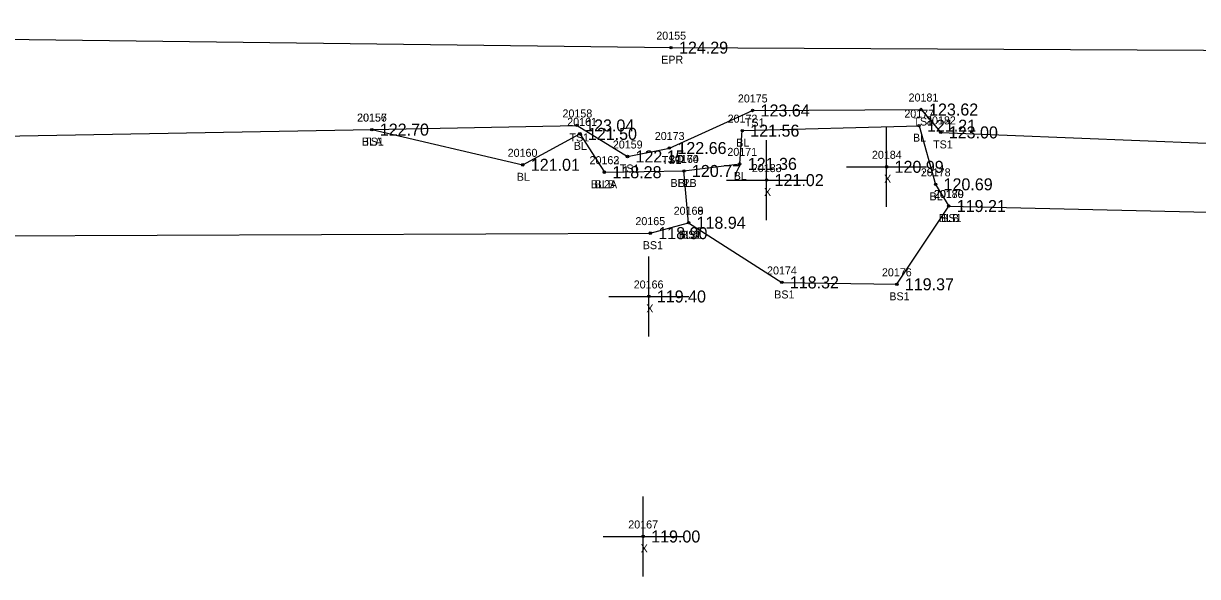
# Model space of a CAD drawing. Extents: x 2375812 to 2377225, y 1024470 to 1025135.
# Drawn here: x 2376784.6 to 2376931.3, y 1024846.4 to 1024915.5 of the extents above; entities that cross this region are included whole.
import ezdxf

# ---------------------------------------------------------------- set-up
doc = ezdxf.new("R2010")
doc.units = 0
for name, color, linetype in [('RD_DTM_BkLn1', 7, 'Continuous'), ('RD_DTM_BkLn2', 7, 'Continuous'), ('RD_DTM_BkLn_txCode', 7, 'Continuous'), ('RD_EX_Misc', 7, 'Continuous'), ('RD_EX_Misc_txCode', 7, 'Continuous'), ('RD_EX_Road', 7, 'Continuous'), ('RD_EX_Road_txCode', 7, 'Continuous'), ('RD_EX_TX_Misc_ELEV', 7, 'Continuous'), ('RD_EX_TX_Road_ELEV', 7, 'Continuous'), ('RD_SMD_Locator', 7, 'Continuous')]:
    doc.layers.add(name, color=color, linetype=linetype)

msp = doc.modelspace()

# ---------------------------------------------------------------- linework, layer by layer
at = {"layer": 'RD_DTM_BkLn1'}
msp.add_line((2376857.22, 1024896.9), (2376867.15, 1024897.05), dxfattribs=at)
for points in [[(2376828.16, 1024902.22), (2376847.02, 1024897.82), (2376854.15, 1024901.69), (2376857.22, 1024896.9)], [(2376867.73, 1024890.58), (2376867.15, 1024897.05), (2376874.13, 1024897.94), (2376874.44, 1024902.09), (2376896.52, 1024902.71), (2376898.59, 1024895.38), (2376900.24, 1024892.67)]]:
    msp.add_lwpolyline(points, dxfattribs=at)
at = {"layer": 'RD_DTM_BkLn2'}
for points in [[(2376561.53, 1024913.62), (2376561.38, 1024909.35), (2376658.21, 1024899.77), (2376672.96, 1024897.91), (2376688.03, 1024903.17), (2376760.99, 1024901.04), (2376828.16, 1024902.22), (2376853.81, 1024902.74), (2376860.1, 1024898.86), (2376865.34, 1024899.92), (2376875.73, 1024904.61), (2376896.78, 1024904.73), (2376899.24, 1024901.87), (2376965.55, 1024899.2), (2377063.48, 1024900.56), (2377114.6, 1024898.84), (2377167.13, 1024900.76), (2377217.62, 1024901.12)], [(2376543.21, 1024910.85), (2376558.6, 1024896.28), (2376588.49, 1024894.01), (2376656.25, 1024894.1), (2376679.22, 1024888.45), (2376688.36, 1024892.22), (2376760.25, 1024888.88), (2376862.95, 1024889.28), (2376867.73, 1024890.58), (2376879.38, 1024883.12), (2376893.75, 1024882.89), (2376900.24, 1024892.67), (2376965.04, 1024891.16), (2377064.46, 1024895.27), (2377115.01, 1024893.54), (2377167.33, 1024895.41), (2377217.32, 1024894.83)]]:
    msp.add_lwpolyline(points, dxfattribs=at)
at = {"layer": 'RD_EX_Misc'}
for p, q in [((2376892.47, 1024892.57), (2376892.47, 1024902.57)), ((2376877.48, 1024890.91), (2376877.48, 1024900.91)), ((2376887.47, 1024897.57), (2376897.47, 1024897.57)), ((2376872.48, 1024895.91), (2376882.48, 1024895.91)), ((2376862.77, 1024876.37), (2376862.77, 1024886.37)), ((2376857.77, 1024881.37), (2376867.77, 1024881.37)), ((2376862.06, 1024846.38), (2376862.06, 1024856.38)), ((2376857.06, 1024851.38), (2376867.06, 1024851.38))]:
    msp.add_line(p, q, dxfattribs=at)
at = {"layer": 'RD_EX_Road'}
msp.add_lwpolyline([(2376561.38, 1024915.36), (2376658.71, 1024915.48), (2376761.9, 1024913.76), (2376865.54, 1024912.46), (2376965.34, 1024911.98), (2377063.07, 1024911.1), (2377113.55, 1024910.69), (2377167.38, 1024909.96), (2377217.4, 1024910.82)], dxfattribs=at)
at = {"layer": 'RD_SMD_Locator'}
for centre in [(2376865.54, 1024912.46), (2376875.73, 1024904.61), (2376896.78, 1024904.73), (2376853.81, 1024902.74), (2376896.52, 1024902.71), (2376828.16, 1024902.22), (2376828.16, 1024902.22), (2376854.15, 1024901.69), (2376874.44, 1024902.09), (2376899.24, 1024901.87), (2376865.34, 1024899.92), (2376860.1, 1024898.86), (2376847.02, 1024897.82), (2376857.22, 1024896.9), (2376857.22, 1024896.9), (2376867.15, 1024897.05), (2376867.15, 1024897.05), (2376874.13, 1024897.94), (2376892.47, 1024897.57), (2376877.48, 1024895.91), (2376898.59, 1024895.38), (2376900.24, 1024892.67), (2376900.24, 1024892.67), (2376867.73, 1024890.58), (2376867.73, 1024890.58), (2376862.95, 1024889.28), (2376879.38, 1024883.12), (2376893.75, 1024882.89), (2376862.77, 1024881.37), (2376862.06, 1024851.38)]:
    msp.add_circle(centre, 0.15, dxfattribs=at)

# ---------------------------------------------------------------- texts
at = {"layer": 'RD_DTM_BkLn_txCode'}
for s, p in [('20175', (2376873.89, 1024905.61)), ('20181', (2376895.22, 1024905.73)), ('20158', (2376851.98, 1024903.74)), ('20177', (2376894.69, 1024903.71)), ('20156', (2376826.31, 1024903.22)), ('20157', (2376826.33, 1024903.22)), ('20161', (2376852.57, 1024902.69)), ('20172', (2376872.61, 1024903.09)), ('TS1', (2376874.77, 1024902.61)), ('TS1', (2376895.82, 1024902.73)), ('20182', (2376897.4, 1024902.87)), ('TS1', (2376852.85, 1024900.74)), ('20173', (2376863.51, 1024900.92)), ('BL', (2376895.77, 1024900.71)), ('BLA', (2376826.92, 1024900.22)), ('TS1', (2376827.2, 1024900.22)), ('BL', (2376853.39, 1024899.69)), ('20159', (2376858.27, 1024899.86)), ('20171', (2376872.58, 1024898.94)), ('BL', (2376873.69, 1024900.09)), ('TS1', (2376898.28, 1024899.87)), ('20160', (2376845.13, 1024898.82)), ('20162', (2376855.36, 1024897.9)), ('20163', (2376855.36, 1024897.9)), ('TS1', (2376864.38, 1024897.92)), ('20170', (2376865.28, 1024898.05)), ('20164', (2376865.29, 1024898.05)), ('TS1', (2376859.14, 1024896.86)), ('BL', (2376873.37, 1024895.94)), ('20178', (2376896.75, 1024896.38)), ('BL', (2376846.27, 1024895.82)), ('BL2A', (2376855.53, 1024894.9)), ('BLB', (2376855.99, 1024894.9)), ('BL2B', (2376865.47, 1024895.05)), ('BL', (2376866.4, 1024895.05)), ('BL', (2376897.83, 1024893.38)), ('20180', (2376898.37, 1024893.67)), ('20179', (2376898.41, 1024893.67)), ('20168', (2376865.87, 1024891.58)), ('20169', (2376865.87, 1024891.58)), ('20165', (2376861.09, 1024890.28)), ('BLB', (2376899.01, 1024890.67)), ('BS1', (2376899.3, 1024890.67)), ('BS1', (2376866.78, 1024888.58)), ('BS1', (2376862.01, 1024887.28)), ('BLA', (2376866.49, 1024888.58)), ('20174', (2376877.54, 1024884.12)), ('20176', (2376891.89, 1024883.89)), ('BS1', (2376878.43, 1024881.12)), ('BS1', (2376892.81, 1024880.89))]:
    msp.add_text(s, height=1, dxfattribs=at).set_placement(p)
at = {"layer": 'RD_EX_Misc_txCode'}
for s, p in [('20184', (2376890.64, 1024898.57)), ('20183', (2376875.64, 1024896.91)), ('X', (2376892.16, 1024895.57)), ('X', (2376877.16, 1024893.91)), ('20166', (2376860.88, 1024882.37)), ('X', (2376862.45, 1024879.37)), ('20167', (2376860.2, 1024852.38)), ('X', (2376861.75, 1024849.38))]:
    msp.add_text(s, height=1, dxfattribs=at).set_placement(p)
at = {"layer": 'RD_EX_Road_txCode'}
for s, p in [('20155', (2376863.7, 1024913.46)), ('EPR', (2376864.31, 1024910.46))]:
    msp.add_text(s, height=1, dxfattribs=at).set_placement(p)
at = {"layer": 'RD_EX_TX_Misc_ELEV'}
for s, p in [('123.64', (2376876.73, 1024903.86)), ('123.62', (2376897.78, 1024903.98)), ('122.70', (2376829.16, 1024901.47)), ('122.70', (2376829.16, 1024901.47)), ('123.04', (2376854.81, 1024901.99)), ('121.56', (2376875.44, 1024901.34)), ('121.21', (2376897.52, 1024901.96)), ('121.50', (2376855.15, 1024900.94)), ('123.00', (2376900.24, 1024901.12)), ('122.66', (2376866.34, 1024899.17)), ('121.01', (2376848.02, 1024897.07)), ('122.15', (2376861.1, 1024898.11)), ('121.36', (2376875.13, 1024897.19)), ('118.28', (2376858.22, 1024896.15)), ('118.28', (2376858.22, 1024896.15)), ('120.77', (2376868.15, 1024896.3)), ('120.77', (2376868.15, 1024896.3)), ('120.99', (2376893.47, 1024896.82)), ('121.02', (2376878.48, 1024895.16)), ('120.69', (2376899.59, 1024894.63)), ('119.21', (2376901.24, 1024891.92)), ('119.21', (2376901.24, 1024891.92)), ('118.94', (2376868.73, 1024889.83)), ('118.94', (2376868.73, 1024889.83)), ('118.90', (2376863.95, 1024888.53)), ('118.32', (2376880.38, 1024882.37)), ('119.37', (2376894.75, 1024882.14)), ('119.40', (2376863.77, 1024880.62)), ('119.00', (2376863.06, 1024850.63))]:
    msp.add_text(s, height=1.5, dxfattribs=at).set_placement(p)
at = {"layer": 'RD_EX_TX_Road_ELEV'}
msp.add_text('124.29', height=1.5, dxfattribs=at).set_placement((2376866.54, 1024911.71))

doc.saveas('drawing.dxf')
